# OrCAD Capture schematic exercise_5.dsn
size A
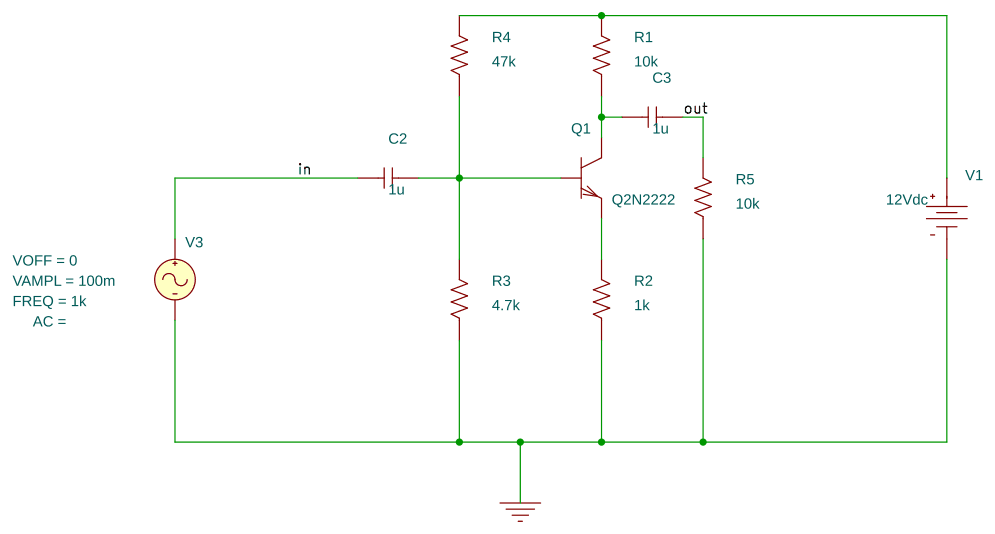
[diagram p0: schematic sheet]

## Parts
C2  1u  [cap196]
C3  1u  [cap196]
Q1  Q2N2222  [TO18]
R1  10k  [AXRC05]
R2  1k  [AXRC05]
R3  4.7k  [AXRC05]
R4  47k  [AXRC05]
R5  10k  [AXRC05]
V1  VDC
V3  VSIN

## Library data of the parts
C2 C3 = C
Q1 = Q2N2222
R1-R5 = R
V1 = VDC: DC: 12Vdc
V3 = VSIN: FREQ: 1k; VAMPL: 100m; VOFF: 0

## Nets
0: R2.1 R3.1 R5.1 V1.1(-) V3.2(-)
in: C2.1 V3.1(+)
out: C3.2 R5.2
N00633: C3.1 Q1.3(c) R1.1
N00637: Q1.1(e) R2.2
N00647: R1.2 R4.2 V1.0(+)
N00674: C2.2 Q1.2(b) R3.2 R4.1
